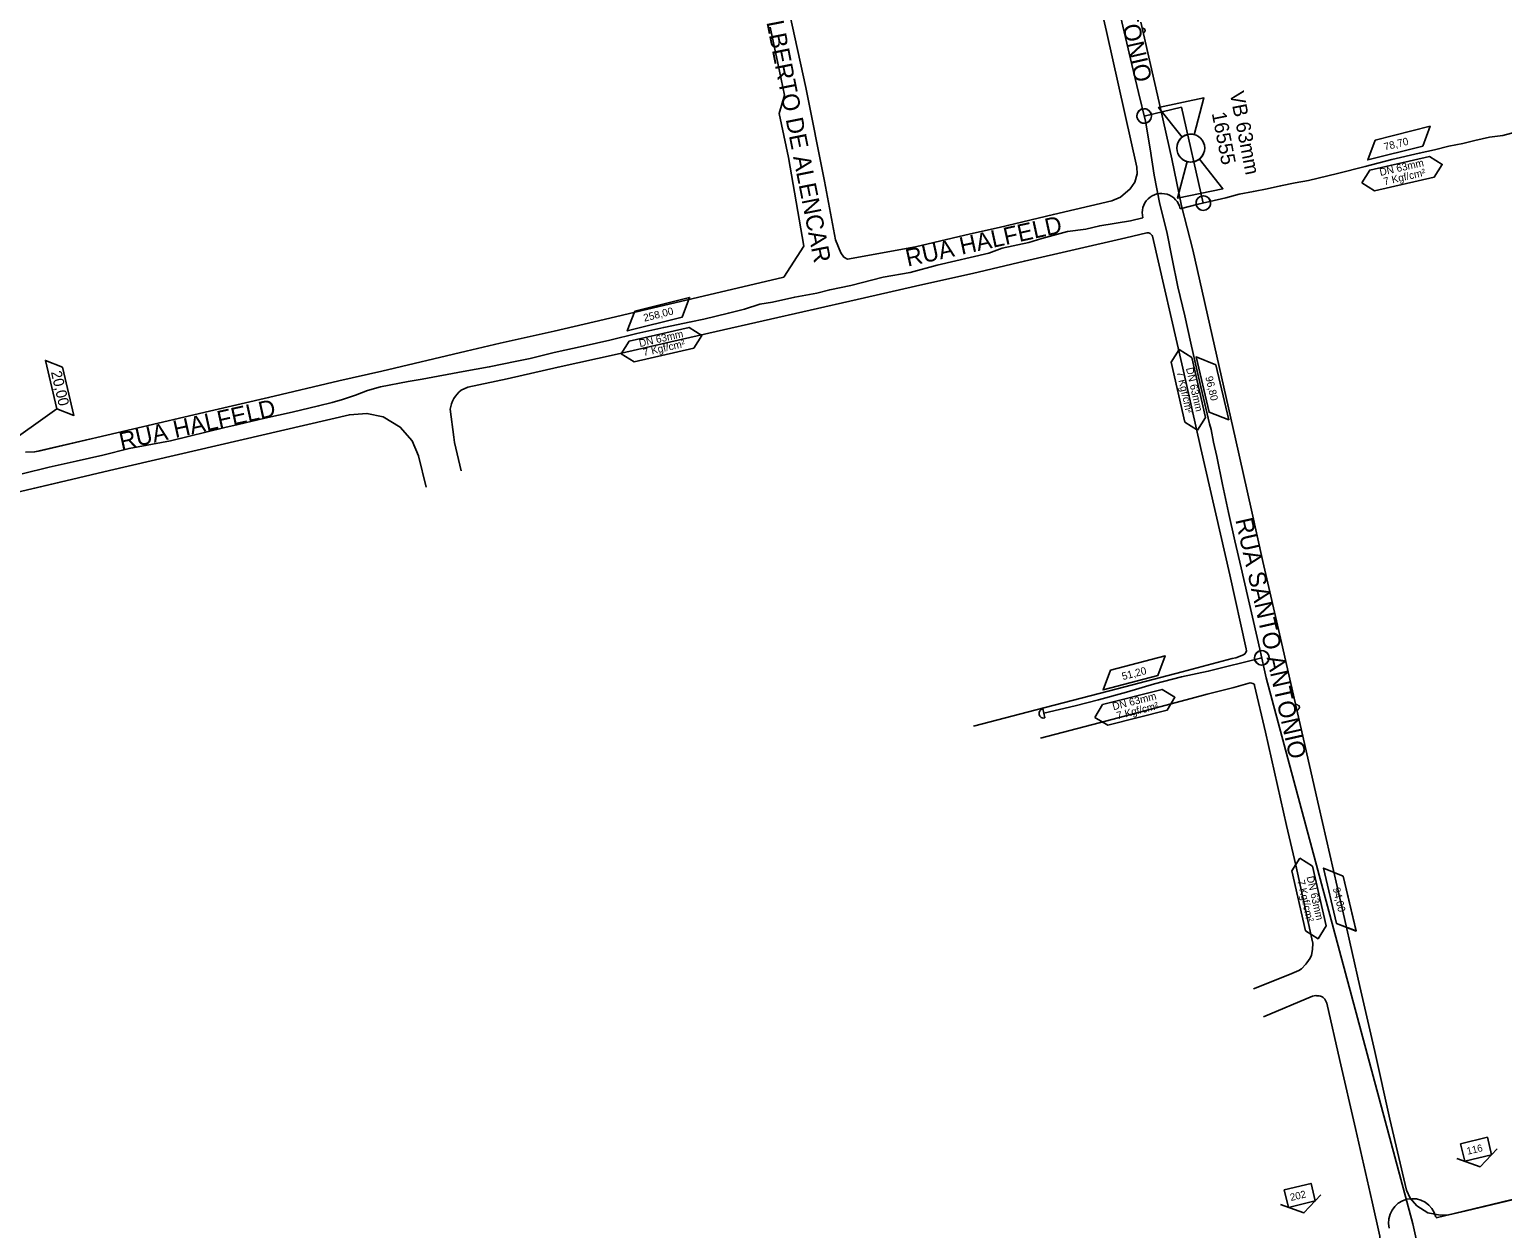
# Model space of a CAD drawing. Extents: x 656692 to 673945, y 7585994 to 7599066.
# Drawn here: x 669416 to 670030, y 7593584 to 7594083 of the extents above; entities that cross this region are included whole.
import ezdxf

# ---------------------------------------------------------------- set-up
doc = ezdxf.new("R2010")
doc.units = 0
for name, color, linetype in [('FORMATO', 7, 'Continuous'), ('LOGRADOURO', 7, 'Continuous'), ('LOGRADOURO_TEXTO', 7, 'Continuous'), ('NUM_REF', 7, 'Continuous'), ('SIMBOLO', 7, 'Continuous'), ('TEXTO', 7, 'Continuous'), ('TUBO_PEAD_GN_63', 7, 'Continuous'), ('VALVULA_PEAD_63', 7, 'Continuous')]:
    doc.layers.add(name, color=color, linetype=linetype)

# ---------------------------------------------------------------- blocks, each defined once
blk = doc.blocks.new('NUM_REF_1')
at = {"layer": 'NUM_REF'}
blk.add_lwpolyline([(-4.3125, 0.9375), (0, 3.75), (4.3125, 0.9375)], dxfattribs=at)
blk.add_lwpolyline([(2.875, -1.875), (2.875, 1.875), (-2.875, 1.875), (-2.875, -1.875)], close=True, dxfattribs=at)
blk = doc.blocks.new('VALVULA_PEAD_DN_16')
at = {"layer": 'VALVULA_PEAD_63'}
for points in [[(-0.0374, 0.0187), (-0.1395, 0.0698), (-0.1395, -0.0698), (-0.0374, -0.0187)], [(-0.0374, -0.0187), (-0.1395, -0.0698), (-0.1395, 0.0698), (-0.0374, 0.0187)], [(0.0374, -0.0187), (0.1395, -0.0698), (0.1395, 0.0698), (0.0374, 0.0187)], [(0.0374, -0.0187), (0.1395, -0.0698), (0.1395, 0.0698), (0.0374, 0.0187)]]:
    blk.add_lwpolyline(points, dxfattribs=at)
blk.add_circle((0, 0), 0.0419, dxfattribs=at)
for start, end in [(90, 270), (153.4349, 206.5651), (270, 90), (333.4349, 26.5651)]:
    blk.add_arc((0, 0), 0.0419, start, end, dxfattribs=at)
blk = doc.blocks.new('INTERLIGACAO_9')
at = {"layer": 'SIMBOLO'}
blk.add_circle((0, 0), 4.19, dxfattribs=at)
for start, end in [(0, 180), (180, 0)]:
    blk.add_arc((0, 0), 4.19, start, end, dxfattribs=at)

msp = doc.modelspace()

# ---------------------------------------------------------------- linework, layer by layer
at = {"layer": 'LOGRADOURO'}
for points in [[(669844.29, 7594174.15), (669848.99, 7594153.03), (669865.07, 7594082.65), (669877.69, 7594026.09), (669877.77, 7594023.39), (669876.85, 7594019.84), (669874.94, 7594017.07), (669870.92, 7594013.64), (669867.24, 7594012.12), (669842.96, 7594006.39), (669820.31, 7594000.97), (669808.37, 7593998.31), (669785.43, 7593992.94), (669757.11, 7593987.72), (669755.63, 7593988.6), (669754.37, 7593990.37), (669752.09, 7593995.89), (669747.5, 7594020.25), (669739.77, 7594059.28), (669730.61, 7594101.25)], [(670054.05, 7593600.53), (670014.86, 7593591.25), (670007.67, 7593589.55), (670004.06, 7593589.43), (669998.91, 7593590.43), (669994.38, 7593593.32), (669991.49, 7593596.49), (669989.98, 7593599.75), (669983.02, 7593629.46), (669976.86, 7593657.59), (669970.52, 7593684.64), (669964.25, 7593713.03), (669953.47, 7593759.69), (669937.96, 7593827.99), (669930.18, 7593861.81), (669925.4, 7593883.17), (669918.74, 7593912.93), (669910.99, 7593947.33), (669901.02, 7593991.61), (669896.23, 7594010.06), (669892.29, 7594029.59), (669886.33, 7594056.05), (669879.3, 7594086.5)], [(669724.96, 7594084.4), (669728.09, 7594069.45), (669730.91, 7594056.09), (669728.74, 7594048.51), (669732.53, 7594030.09), (669739, 7593993.14), (669730.61, 7593980.24), (669706.42, 7593974.57), (669678.63, 7593968.11), (669655.73, 7593962.63), (669634.96, 7593957.81), (669612.4, 7593952.7), (669598.29, 7593949.48), (669563.16, 7593941.16), (669545.24, 7593937.06), (669515.94, 7593930.07), (669491.39, 7593924.43), (669437.87, 7593911.91), (669420.74, 7593907.83), (669418.63, 7593907.53), (669414.71, 7593907.35)], [(669881.87, 7593998.7), (669873.15, 7593996.7), (669830.88, 7593986.95), (669809.19, 7593981.82), (669788.58, 7593977.18), (669761.18, 7593970.96), (669702.38, 7593957.56), (669683.49, 7593953.31), (669661.12, 7593948.15), (669636.57, 7593942.78), (669615.33, 7593937.93), (669598.95, 7593934.44), (669596.17, 7593933.21)], [(669923.29, 7593825.36), (669916.45, 7593856.17), (669904.4, 7593908.88), (669896.84, 7593942.3), (669884.25, 7593997.3)], [(669591.59, 7593925.24), (669593.18, 7593913.59), (669593.48, 7593911.42), (669596.26, 7593899.62)], [(669449.72, 7593899.68), (669549.65, 7593922.95), (669556.92, 7593923.51), (669563.65, 7593922.08), (669570.79, 7593917.78), (669575.75, 7593912.08), (669578.46, 7593905.76), (669581.67, 7593892.75)], [(669441.37, 7593912.72), (669418.63, 7593907.53), (669418.44, 7593907.49)], [(669245.77, 7593636.42), (669233.12, 7593691.69), (669211.67, 7593783.91), (669202.22, 7593824.61), (669201.49, 7593829.75), (669202.2, 7593834), (669203.5, 7593837.14), (669206.1, 7593840.48), (669210.1, 7593843.14), (669213.38, 7593844.46), (669240.77, 7593850.86), (669255.13, 7593854.09), (669283.23, 7593860.74), (669319.18, 7593869.03), (669362.65, 7593879.26), (669372.9, 7593881.61), (669429.1, 7593894.88)], [(669449.72, 7593899.68), (669429.1, 7593894.88), (669416.78, 7593891.89)], [(669809.66, 7593793.21), (669835.71, 7593800), (669869.45, 7593808.79), (669896.62, 7593815.85), (669917.4, 7593821.31), (669918.89, 7593821.67), (669922.05, 7593822.89)], [(669924.93, 7593811.17), (669918.16, 7593809.33), (669906.96, 7593806.44), (669900.38, 7593804.68), (669883.1, 7593800.05), (669862.01, 7593794.59), (669837.49, 7593788.13)], [(669926.31, 7593683.67), (669941.27, 7593689.68), (669945.19, 7593691.36), (669946.29, 7593692.09), (669948.03, 7593693.95), (669948.57, 7593694.61), (669949.83, 7593696.53), (669950.38, 7593697.79), (669950.91, 7593700.17), (669950.94, 7593702.81), (669950.62, 7593704.58), (669943.86, 7593735.31), (669940.06, 7593751.81), (669931.24, 7593790.69), (669926.77, 7593810.14)], [(669952.19, 7593680.87), (669950.89, 7593680.67), (669930.48, 7593671.98)], [(669948.03, 7593575.49), (669960.57, 7593578.21), (669968.06, 7593575.91), (669977.72, 7593578.17), (669978.78, 7593578.62), (669978.93, 7593580.62), (669975.67, 7593594.92), (669968.75, 7593625.45), (669962.29, 7593653.78), (669956.77, 7593677.72)]]:
    msp.add_lwpolyline(points, dxfattribs=at)
for centre, radius, start, end in [((669882.26, 7593997), 1.74, 55.89672, 102.89415), ((669881.5, 7593995.88), 3.09, 27.26629, 55.89672), ((669604.33, 7593923.21), 12.9, 129.25696, 170.98161), ((669921.27, 7593824.83), 2.09, 291.94053, 14.77171), ((669925.1, 7593808.61), 2.56, 68.17209, 93.80056), ((669925.6, 7593809.87), 1.2, 12.94246, 68.17209), ((669952.41, 7593674.18), 6.69, 74.68903, 91.89301), ((669953.64, 7593678.14), 2.55, 40.55211, 77.82078), ((669951.86, 7593676.29), 5.12, 16.28051, 43.36065)]:
    msp.add_arc(centre, radius, start, end, dxfattribs=at)
at = {"layer": 'SIMBOLO'}
for points in [[(669971.41, 7594019.6), (669974.74, 7594024.9), (669999.63, 7594030.6), (670004.93, 7594027.28), (670001.6, 7594021.98), (669976.71, 7594016.28), (669971.41, 7594019.6)], [(669662.91, 7593948.32), (669666.24, 7593953.62), (669691.13, 7593959.32), (669696.43, 7593956), (669693.11, 7593950.7), (669668.21, 7593945), (669662.91, 7593948.32)], [(669895.33, 7593950.07), (669900.63, 7593946.74), (669906.27, 7593921.83), (669902.94, 7593916.54), (669897.64, 7593919.88), (669892, 7593944.78), (669895.33, 7593950.07)], [(669860.23, 7593796.79), (669863.43, 7593802.17), (669888.18, 7593808.45), (669893.56, 7593805.25), (669890.36, 7593799.87), (669865.61, 7593793.59), (669860.23, 7593796.79)], [(669945.58, 7593738.14), (669950.87, 7593734.8), (669956.52, 7593709.9), (669953.18, 7593704.6), (669947.89, 7593707.94), (669942.24, 7593732.84), (669945.58, 7593738.14)]]:
    msp.add_lwpolyline(points, dxfattribs=at)
at = {"layer": 'TEXTO'}
msp.add_line((669405.03, 7593909.13), (669427.7, 7593925.43), dxfattribs=at)
for points in [[(669977.03, 7594037.4), (669999.82, 7594043.14), (669996.79, 7594034.92), (669973.86, 7594029.14), (669977.03, 7594037.4)], [(669977.03, 7594037.4), (669999.83, 7594043.14), (669996.79, 7594034.92), (669973.86, 7594029.14), (669977.03, 7594037.4)], [(669668.53, 7593966.12), (669691.33, 7593971.85), (669688.3, 7593963.63), (669665.36, 7593957.86), (669668.53, 7593966.12)], [(669668.54, 7593966.12), (669691.33, 7593971.85), (669688.3, 7593963.63), (669665.36, 7593957.86), (669668.54, 7593966.12)], [(669430.16, 7593942.71), (669434.86, 7593922.66), (669427.7, 7593925.43), (669422.97, 7593945.61), (669430.16, 7593942.71)], [(669910.58, 7593943.73), (669915.95, 7593920.85), (669907.78, 7593924.01), (669902.38, 7593947.04), (669910.58, 7593943.73)], [(669910.58, 7593943.73), (669915.95, 7593920.85), (669907.78, 7593924.01), (669902.38, 7593947.04), (669910.58, 7593943.73)], [(669866.69, 7593816.57), (669889.43, 7593822.52), (669886.47, 7593814.27), (669863.59, 7593808.28), (669866.69, 7593816.57)], [(669866.69, 7593816.57), (669889.43, 7593822.52), (669886.47, 7593814.27), (669863.6, 7593808.28), (669866.69, 7593816.57)], [(669963.66, 7593730.7), (669969.03, 7593707.82), (669960.86, 7593710.98), (669955.46, 7593734.01), (669963.66, 7593730.7)], [(669963.66, 7593730.7), (669969.03, 7593707.81), (669960.86, 7593710.98), (669955.46, 7593734), (669963.66, 7593730.7)]]:
    msp.add_lwpolyline(points, dxfattribs=at)
at = {"layer": 'TUBO_PEAD_GN_63'}
msp.add_line((669838.51, 7593800.48), (669839.39, 7593796.58), dxfattribs=at)
for points in [[(669870.3, 7594091.44), (669873, 7594080.12), (669875.65, 7594068.83), (669878.41, 7594057.17), (669881.26, 7594045.27), (669883.19, 7594033.68), (669884.84, 7594022.71), (669887.29, 7594010.69), (669890.14, 7593999.09), (669892.41, 7593987.88), (669894.79, 7593976.17), (669897.63, 7593964.14), (669900.11, 7593952.82), (669902.84, 7593941.09), (669905.45, 7593929.86), (669907.92, 7593919.2), (669908.6, 7593916.77), (669909.63, 7593911.48), (669910.97, 7593905.54), (669913.35, 7593893.92), (669915.91, 7593882.26), (669918.52, 7593870.38), (669921.15, 7593859.15), (669923.84, 7593847.58), (669926.27, 7593836.81), (669928.97, 7593825.24), (669931.57, 7593813.26)], [(669880.73, 7594047.42), (669896.25, 7594051.06), (669905.38, 7594011.13)], [(669895.74, 7594008.8), (669895.74, 7594008.8), (669903.19, 7594010.63), (669914.81, 7594013.28), (669920.38, 7594014.81), (669926.28, 7594016), (669931.97, 7594017.14), (669937.59, 7594018.3), (669943.63, 7594019.55), (669949.22, 7594020.59), (669961.33, 7594023.5), (669972.79, 7594026.32), (669983.98, 7594029.24), (669995.31, 7594031.87), (670001.7, 7594033.39), (670007.65, 7594034.79), (670013.47, 7594035.93), (670018.54, 7594037.2), (670024.61, 7594038.57), (670030.14, 7594039.35), (670042.04, 7594042.5), (670048.59, 7594044.03)], [(669413.24, 7593898.35), (669424.59, 7593901.11), (669435.74, 7593903.53), (669446.92, 7593906.14), (669457.85, 7593908.89), (669475.17, 7593912.1), (669497.8, 7593917.63), (669503.35, 7593918.93), (669514.44, 7593921.52), (669525.82, 7593924.08), (669536.81, 7593926.61), (669542.4, 7593928.08), (669546.77, 7593929.26), (669552.22, 7593931.11), (669557.21, 7593933.03), (669562.53, 7593934.56), (669574.17, 7593936.78), (669579.91, 7593937.78), (669596.97, 7593940.95), (669607.89, 7593942.9), (669619.36, 7593945.22), (669624.89, 7593946.43), (669634.99, 7593948.83), (669647.05, 7593951.5), (669658.13, 7593954.02), (669669.41, 7593956.81), (669680.56, 7593959.33), (669691.92, 7593961.59), (669697.28, 7593962.83), (669707.5, 7593965.31), (669714.2, 7593966.88), (669720.66, 7593969.08), (669725.88, 7593969.83), (669735.14, 7593971.99), (669744.32, 7593973.58), (669749.73, 7593975.01), (669758.48, 7593976.76), (669772.07, 7593980.3), (669783.31, 7593982.28), (669794.45, 7593985.32), (669816.07, 7593990.33), (669821.62, 7593992.37), (669832.69, 7593994.78), (669838.08, 7593996.32), (669848.86, 7593999.24), (669856.44, 7594000.28), (669862.23, 7594001.67), (669874.99, 7594003.78), (669880.21, 7594005.05)], [(669838.95, 7593798.53), (669851.93, 7593801.66), (669861.76, 7593804.2), (669873.31, 7593807.39), (669885.09, 7593810.83), (669896.23, 7593813.71), (669907.41, 7593816.06), (669929.75, 7593821.65)], [(670036.5, 7593394.83), (670033.94, 7593405.1), (670031.92, 7593413.12), (670030, 7593420.91), (670028.04, 7593428.76), (670026.15, 7593436.44), (670024, 7593445.14), (670021.9, 7593454.01), (670019.78, 7593463.14), (670018.49, 7593468.48), (670017.25, 7593473.7), (670016.34, 7593477.75), (670014.68, 7593485.08), (670012.07, 7593496.69), (670009.27, 7593509.09), (670007.08, 7593519.11), (670004.85, 7593529.26), (670002.82, 7593538.9), (670000.97, 7593547.38), (669998.98, 7593556.44), (669996.99, 7593565.7), (669995.51, 7593572.61), (669992.66, 7593585.75), (669931.57, 7593813.26)], [(670045.08, 7593598.51), (670002.33, 7593588.33)]]:
    msp.add_lwpolyline(points, dxfattribs=at)
for centre, radius, start, end in [((669887.92, 7594007.16), 7.99, 11.88409, 195.32614), ((669838.95, 7593798.53), 2, 102.75735, 282.75735), ((669992.54, 7593586.27), 10, 13.3955, 193.3955)]:
    msp.add_arc(centre, radius, start, end, dxfattribs=at)

# ---------------------------------------------------------------- block references
at = {"layer": 'FORMATO', "xscale": 1.9999999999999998, "yscale": 1.9999999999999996, "rotation": -166.54259928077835}
for p in [(670018.99, 7593616.87), (669945.55, 7593597.62)]:
    msp.add_blockref('NUM_REF_1', p, dxfattribs=at)
at = {"layer": 'SIMBOLO', "xscale": 0.7229249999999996, "yscale": 0.7229249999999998, "rotation": 166.312122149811}
for p in [(669880.73, 7594047.42), (669905.38, 7594011.13), (669929.75, 7593821.65)]:
    msp.add_blockref('INTERLIGACAO_9', p, dxfattribs=at)
at = {"layer": 'VALVULA_PEAD_63', "xscale": 138.56062500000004, "yscale": 138.560625, "rotation": 101.81616978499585}
msp.add_blockref('VALVULA_PEAD_DN_16', (669900.14, 7594034.04), dxfattribs=at)

# ---------------------------------------------------------------- texts
for s, height, rotation, p in [('VB 63mm', 6, 281.04801, (669916.35, 7594057.11)), ('16555', 6, 281.04801, (669908.86, 7594048.57)), ('116', 3, 13.4574, (670015.49, 7593614.56)), ('202', 3, 13.4574, (669941.9, 7593595.29))]:
    msp.add_text(s, height=height, rotation=rotation).set_placement(p)
at = {"layer": 'LOGRADOURO_TEXTO'}
for s, rotation, p in [('RUA SANTO ANTÔNIO', 282.78963, (669854.38, 7594161.15)), ('RUA GILBERTO DE ALENCAR', 281.20516, (669716.89, 7594119.08)), ('RUA HALFELD', 12.44264, (669782.22, 7593984.64)), ('RUA HALFELD', 12.44264, (669454.63, 7593908.26)), ('RUA SANTO ANTÔNIO', 282.78963, (669918.68, 7593879.15))]:
    msp.add_text(s, height=7.2, rotation=rotation, dxfattribs=at).set_placement(p)
at = {"layer": 'TEXTO'}
for s, height, rotation, p in [('78,70', 3.113, 14.12786, (669981.02, 7594033)), ('DN 63mm', 3.113, 12.89737, (669979.19, 7594022.41)), ('7 Kgf/cm²', 3.113, 12.89737, (669980.82, 7594018.55)), ('258,00', 3.113, 14.12786, (669672.53, 7593961.71)), ('DN 63mm', 3.113, 12.89737, (669670.69, 7593951.13)), ('7 Kgf/cm²', 3.113, 12.89737, (669672.32, 7593947.27)), ('20,00', 4.447, 283.19761, (669425.26, 7593940.74)), ('7 Kgf/cm²', 3.113, 282.77499, (669894.26, 7593940.67)), ('DN 63mm', 3.113, 282.77499, (669898.13, 7593942.29)), ('96,80', 3.113, 283.19761, (669906.21, 7593938.65)), ('51,20', 3.113, 14.66347, (669871.88, 7593812.33)), ('DN 63mm', 3.113, 14.24086, (669867.94, 7593799.78)), ('7 Kgf/cm²', 3.113, 14.24086, (669869.66, 7593795.96)), ('7 Kgf/cm²', 3.113, 282.77499, (669944.51, 7593728.73)), ('DN 63mm', 3.113, 282.77499, (669948.37, 7593730.35)), ('94,00', 3.113, 283.19761, (669959.29, 7593725.61))]:
    msp.add_text(s, height=height, rotation=rotation, dxfattribs=at).set_placement(p)

doc.saveas('drawing.dxf')
